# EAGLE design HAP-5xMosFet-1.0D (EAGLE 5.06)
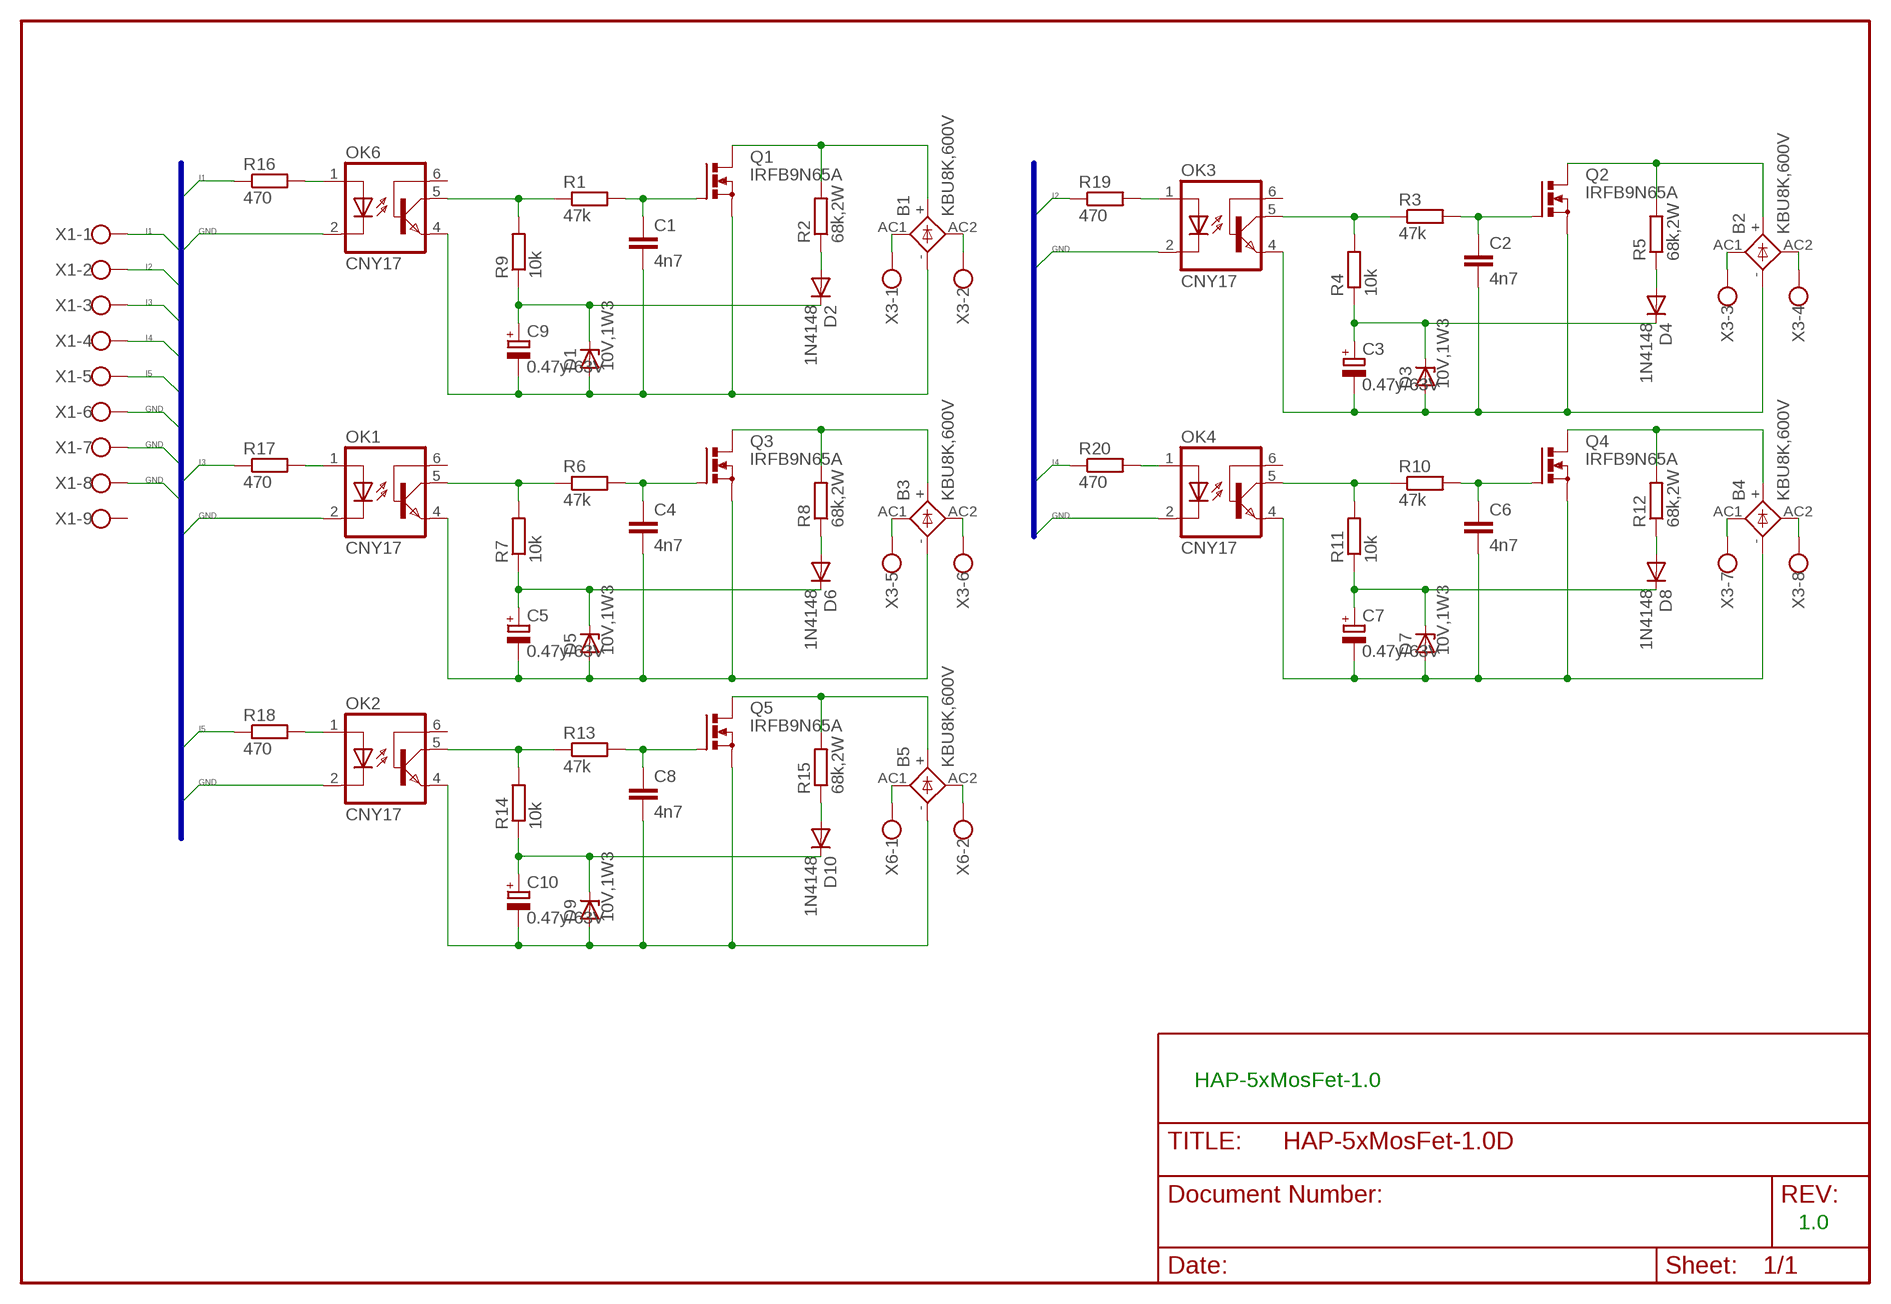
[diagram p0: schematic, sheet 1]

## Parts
B1  KBU8K,600V  KBU  [KBU]
B2  KBU8K,600V  KBU  [KBU]
B3  KBU8K,600V  KBU  [KBU]
B4  KBU8K,600V  KBU  [KBU]
B5  KBU8K,600V  KBU  [KBU]
C1  4n7  C-EU025-025X050  [C025-025X050]
C2  4n7  C-EU025-025X050  [C025-025X050]
C3  0.47y/63V  CPOL-EUE2-5  [E2-5]
C4  4n7  C-EU025-025X050  [C025-025X050]
C5  0.47y/63V  CPOL-EUE2-5  [E2-5]
C6  4n7  C-EU025-025X050  [C025-025X050]
C7  0.47y/63V  CPOL-EUE2-5  [E2-5]
C8  4n7  C-EU025-025X050  [C025-025X050]
C9  0.47y/63V  CPOL-EUE2-5  [E2-5]
C10  0.47y/63V  CPOL-EUE2-5  [E2-5]
D1  10V,1W3  ZENER-DIODEDO34-7  [DO34Z7]
D2  1N4148  BAT81  [DO34-7]
D3  10V,1W3  ZENER-DIODEDO34-7  [DO34Z7]
D4  1N4148  BAT81  [DO34-7]
D5  10V,1W3  ZENER-DIODEDO34-7  [DO34Z7]
D6  1N4148  BAT81  [DO34-7]
D7  10V,1W3  ZENER-DIODEDO34-7  [DO34Z7]
D8  1N4148  BAT81  [DO34-7]
D9  10V,1W3  ZENER-DIODEDO34-7  [DO34Z7]
D10  1N4148  BAT81  [DO34-7]
OK1  CNY17  [DIL06]
OK2  CNY17  [DIL06]
OK3  CNY17  [DIL06]
OK4  CNY17  [DIL06]
OK6  CNY17  [DIL06]
Q1  IRFB9N65A  IRF512  [TO220BV]
Q2  IRFB9N65A  IRF512  [TO220BV]
Q3  IRFB9N65A  IRF512  [TO220BV]
Q4  IRFB9N65A  IRF512  [TO220BV]
Q5  IRFB9N65A  IRF512  [TO220BV]
R1  47k  R-EU_0207/2V  [0207/2V]
R2  68k,2W  R-EU_0411/3V  [0411V]
R3  47k  R-EU_0207/2V  [0207/2V]
R4  10k  R-EU_0207/2V  [0207/2V]
R5  68k,2W  R-EU_0411/3V  [0411V]
R6  47k  R-EU_0207/2V  [0207/2V]
R7  10k  R-EU_0207/2V  [0207/2V]
R8  68k,2W  R-EU_0411/3V  [0411V]
R9  10k  R-EU_0207/2V  [0207/2V]
R10  47k  R-EU_0207/2V  [0207/2V]
R11  10k  R-EU_0207/2V  [0207/2V]
R12  68k,2W  R-EU_0411/3V  [0411V]
R13  47k  R-EU_0207/2V  [0207/2V]
R14  10k  R-EU_0207/2V  [0207/2V]
R15  68k,2W  R-EU_0411/3V  [0411V]
R16  470  R-EU_R0805  [R0805]
R17  470  R-EU_R0805  [R0805]
R18  470  R-EU_R0805  [R0805]
R19  470  R-EU_R0805  [R0805]
R20  470  R-EU_R0805  [R0805]
X1  W237-09P  [W237-9P]
X3  W237-08P  [W237-8P]
X6  W237-08P  [W237-8P]

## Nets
GND: OK1.2(C) OK2.2(C) OK3.2(C) OK4.2(C) OK6.2(C) X1.6 X1.7 X1.8
I1: R16.1 X1.1
I2: R19.1 X1.2
I3: R17.1 X1.3
I4: R20.1 X1.4
I5: R18.1 X1.5
N$1 [Medium]: OK6.5(COL) R1.1 R9.2
N$2 [Medium]: C1.1 Q1.G R1.2
N$3 [Medium]: C9.+ D1.C D2.C R9.1
N$4 [Medium]: OK3.5(COL) R3.1 R4.2
N$5 [Medium]: D2.A R2.1
N$6 [Mains]: B1.+ Q1.D R2.2
N$9 [Medium]: C2.1 Q2.G R3.2
N$10 [Medium]: C3.+ D3.C D4.C R4.1
N$11 [Medium]: D4.A R5.1
N$12 [Mains]: B2.+ Q2.D R5.2
N$15 [Medium]: OK1.5(COL) R6.1 R7.2
N$16 [Medium]: C4.1 Q3.G R6.2
N$17 [Medium]: C5.+ D5.C D6.C R7.1
N$18 [Medium]: D6.A R8.1
N$19 [Mains]: B3.+ Q3.D R8.2
N$22 [Medium]: OK4.5(COL) R10.1 R11.2
N$23 [Medium]: C6.1 Q4.G R10.2
N$24 [Medium]: C7.+ D7.C D8.C R11.1
N$25 [Medium]: D8.A R12.1
N$26 [Mains]: B4.+ Q4.D R12.2
N$29 [Medium]: OK2.5(COL) R13.1 R14.2
N$30 [Medium]: C8.1 Q5.G R13.2
N$31 [Medium]: C10.+ D9.C D10.C R14.1
N$32 [Medium]: D10.A R15.1
N$33 [Mains]: B5.+ Q5.D R15.2
N$36: OK6.1(A) R16.2
N$37: OK1.1(A) R17.2
N$38: OK2.1(A) R18.2
N$39 [Mains]: B1.- C1.2 C9.- D1.A OK6.4(EMI) Q1.S
N$40 [Mains]: B3.- C4.2 C5.- D5.A OK1.4(EMI) Q3.S
N$41 [Mains]: B5.- C8.2 C10.- D9.A OK2.4(EMI) Q5.S
N$42 [Mains]: B2.- C2.2 C3.- D3.A OK3.4(EMI) Q2.S
N$43: OK3.1(A) R19.2
N$44 [Mains]: B4.- C6.2 C7.- D7.A OK4.4(EMI) Q4.S
N$45: OK4.1(A) R20.2
N$71 [Mains]: B1.AC1 X3.1
N$72 [Mains]: B1.AC2 X3.2
N$73 [Mains]: B3.AC1 X3.5
N$74 [Mains]: B3.AC2 X3.6
N$75 [Mains]: B5.AC1 X6.1
N$76 [Mains]: B5.AC2 X6.2
N$77 [Mains]: B2.AC1 X3.3
N$78 [Mains]: B2.AC2 X3.4
N$79 [Mains]: B4.AC1 X3.7
N$80 [Mains]: B4.AC2 X3.8
Unconnected: OK1.6(BAS) OK2.6(BAS) OK3.6(BAS) OK4.6(BAS) OK6.6(BAS) X1.9 X6.3 X6.4 X6.5 X6.6 X6.7 X6.8

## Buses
VCCSUPPLY,GND,O1,O2,O3,O4,O5,O6,O7,O8,I1,I2,I3,I4,I5,I6,I7,I8

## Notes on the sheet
- HAP-5xMosFet-1.0
- 1.0

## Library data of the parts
B1-B5 = rectifier:KBU: DIOTEC RECTIFIER
C1 C2 C4 C6 C8 = rcl:C-EU: CAPACITOR, European symbol
C3 C5 C7 C9 C10 = rcl:CPOL-EU: POLARIZED CAPACITOR, European symbol
D1 D3 D5 D7 D9 = diode:ZENER-DIODE: Z-Diode
D2 D4 D6 D8 D10 = diode:BAT81: DIODE
OK1-OK4 OK6 = optocoupler:CNY17: SIEMENS OPTO COUPLER
Q1-Q5 = transistor-power:IRF512: N-CHANNEL MOS FET
R1-R20 = rcl:R-EU_: RESISTOR, European symbol
X1 = con-wago-508:W237-09P: WAGO SREW CLAMP
X3 X6 = con-wago-508:W237-08P: WAGO SREW CLAMP

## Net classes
1 Mains: width 2.184 mm, clearance 0.508 mm
2 Medium: width 0.508 mm, clearance 0.254 mm

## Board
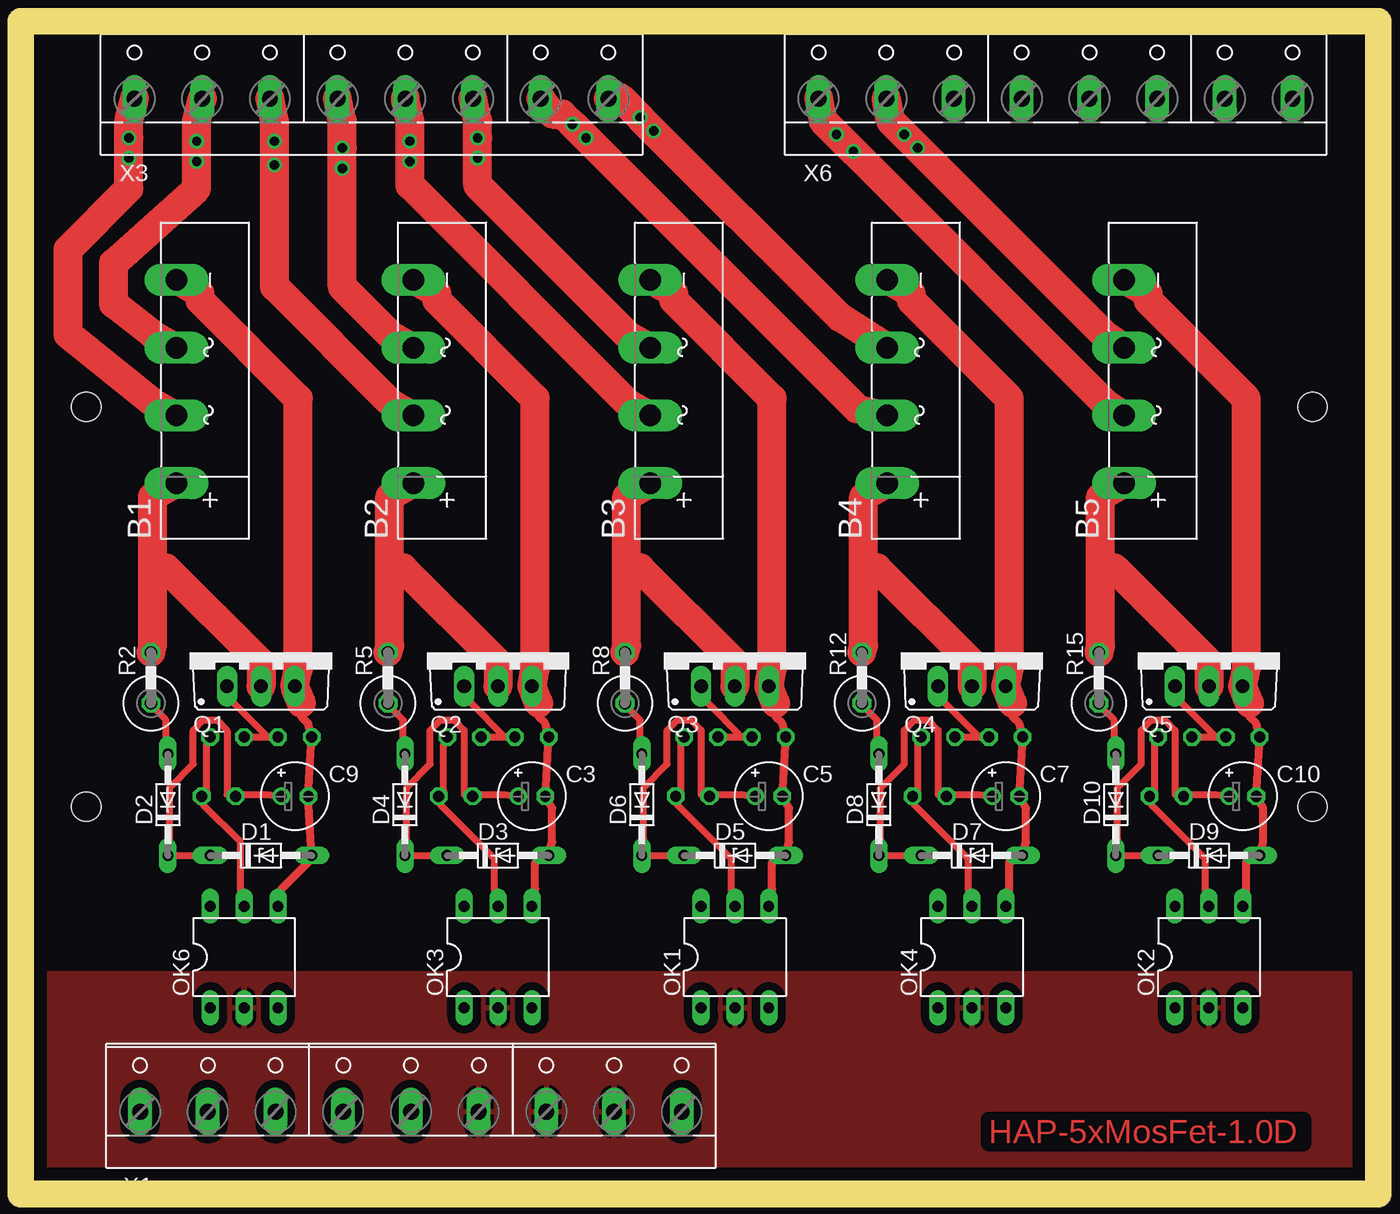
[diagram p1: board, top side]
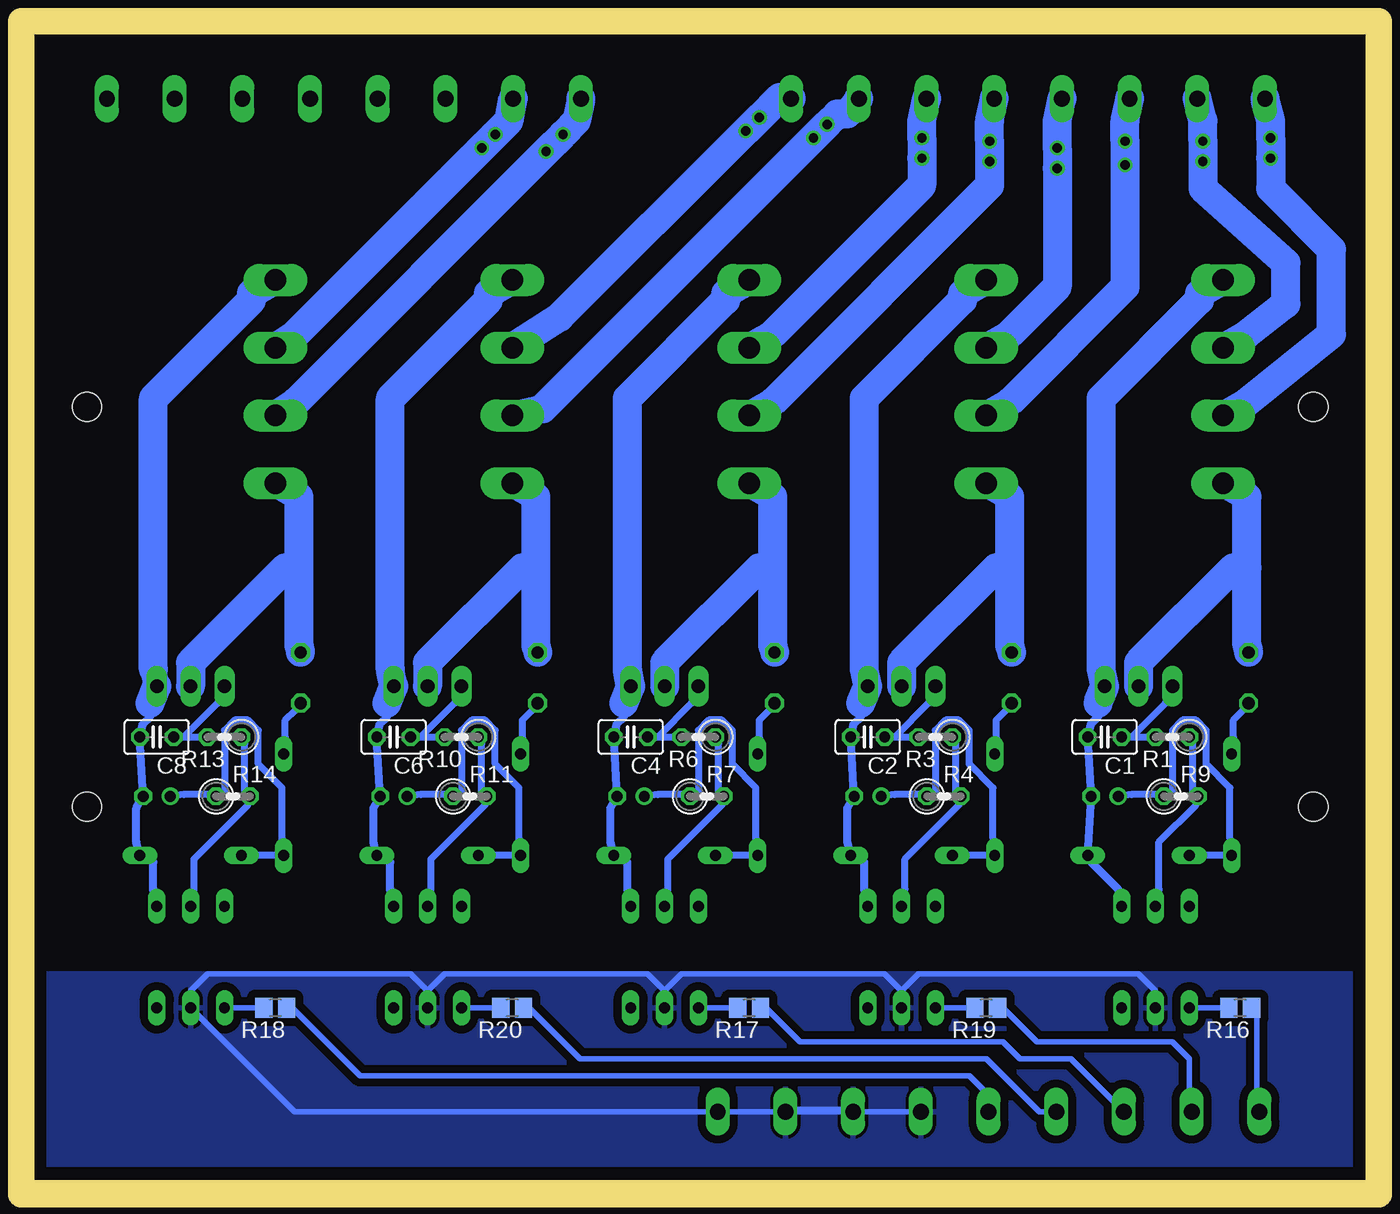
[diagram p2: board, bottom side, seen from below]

Size 100 x 86.08 mm. Coordinates in mm from the lower left corner, seen from the top.
Outline: 100,0 100,86.08 0,86.08 0,0 100,0
Copper layers (1*16): Top 0.035mm / dielectric 1.5mm / Bottom 0.035mm
Design rules "default": minimum track width 10mil, minimum drill 24mil, track to track 8mil, track to pad 8mil, pad to pad 8mil, via to via 8mil, smd to smd 8mil, copper to edge 40mil, drill to drill 8mil, minimum pad ring 10mil, minimum via ring 8mil, stop-mask expansion 4mil, vias tented up to drill 0mil, thermal gap 10mil
Holes 2.2 mm at 3.97,28.05 3.97,58.06 95.98,58.05 95.97,28.05
Milling: 4 lines

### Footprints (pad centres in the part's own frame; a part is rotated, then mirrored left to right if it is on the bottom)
KBU = drill 1.6 long: + -7.62,2.54; - 7.62,2.54; AC1 -2.54,2.54; AC2 2.54,2.54
C025-025X050 = drill 0.813 octagon: 1 -1.27,0; 2 1.27,0
E2-5 = drill 0.813 pad 1.27 round: + -1.016,0 | drill 0.813 pad 1.27 octagon: - 1.016,0
DO34Z7 = drill 0.813 long: A 3.81,0; C -3.81,0
DO34-7 = drill 0.813 long: A 3.81,0; C -3.81,0
DIL06 = drill 0.813 long: 1 -2.54,-3.81; 2 0,-3.81; 3 2.54,-3.81; 4 2.54,3.81; 5 0,3.81; 6 -2.54,3.81
TO220BV = drill 1.016 long: D 0,-2.54; G -2.54,-2.54; S 2.54,-2.54
0207/2V = drill 0.813 octagon: 1 -1.27,0; 2 1.27,0
0411V = drill 0.914 octagon: 1 -2.54,0; 2 1.27,0
R0805 = smd 1.3 x 1.5: 1 -0.85,0; 2 0.85,0
W237-9P = drill 1.194 long: 1 -20.32,-0.635; 2 -15.24,-0.635; 3 -10.16,-0.635; 4 -5.08,-0.635; 5 0,-0.635; 6 5.08,-0.635; 7 10.16,-0.635; 8 15.24,-0.635; 9 20.32,-0.635
W237-8P = drill 1.194 long: 1 -17.78,-0.635; 2 -12.7,-0.635; 3 -7.62,-0.635; 4 -2.54,-0.635; 5 2.54,-0.635; 6 7.62,-0.635; 7 12.7,-0.635; 8 17.78,-0.635

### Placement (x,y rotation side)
B1  13.27,59.95 90 top
B2  31.05,59.95 90 top
B3  48.83,59.95 90 top
B4  66.61,59.95 90 top
B5  84.39,59.95 90 top
C1  19.62,33.28 180 bottom
C2  37.4,33.28 180 bottom
C3  37.4,28.84 0 top
C4  55.18,33.28 180 bottom
C5  55.18,28.84 0 top
C6  72.96,33.28 180 bottom
C7  72.96,28.84 0 top
C8  90.74,33.28 180 bottom
C9  19.62,28.84 0 top
C10  90.74,28.84 0 top
D1  17.08,24.39 0 top
D2  10.09,28.2 90 top
D3  34.86,24.39 0 top
D4  27.88,28.2 90 top
D5  52.64,24.39 0 top
D6  45.66,28.2 90 top
D7  70.42,24.39 0 top
D8  63.44,28.2 90 top
D9  88.2,24.39 0 top
D10  81.22,28.2 90 top
OK1  52.64,16.77 0 top
OK2  88.2,16.77 0 top
OK3  34.86,16.77 0 top
OK4  70.42,16.77 0 top
OK6  15.81,16.77 0 top
Q1  17.08,39.63 0 top
Q2  34.86,39.63 0 top
Q3  52.64,39.63 0 top
Q4  70.42,39.63 0 top
Q5  88.2,39.63 0 top
R1  14.54,33.28 180 bottom
R2  8.82,38.36 90 top
R3  32.32,33.28 180 bottom
R4  31.69,28.84 0 bottom
R5  26.61,38.36 90 top
R6  50.1,33.28 180 bottom
R7  49.47,28.84 0 bottom
R8  44.38,38.36 90 top
R9  13.9,28.84 0 bottom
R10  67.88,33.28 180 bottom
R11  67.25,28.84 0 bottom
R12  62.17,38.36 90 top
R13  85.66,33.28 180 bottom
R14  85.03,28.84 0 bottom
R15  79.95,38.36 90 top
R16  9.46,12.96 180 bottom
R17  46.29,12.96 180 bottom
R18  81.85,12.96 180 bottom
R19  28.51,12.96 180 bottom
R20  64.07,12.96 180 bottom
X1  28.33,5.81 0 top
X3  25.37,81.81 0 top
X6  76.7,81.81 0 top

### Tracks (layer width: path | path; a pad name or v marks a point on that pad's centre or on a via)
GND
  Bottom 0.406: 70.42,14.23 71.69,15.5 86.93,15.5 88.2,14.23 OK2.2 80.41,5.17 X1.6 X1.7 | 70.42,14.23 OK4.2 | 70.42,14.23 69.15,15.5 53.91,15.5 52.64,14.23 | 52.64,14.23 51.37,15.5 36.13,15.5 34.86,14.23 | 34.86,14.23 33.59,15.5 17.08,15.5 15.81,14.23 OK6.2 | X1.7 | X1.7 38.67,5.34 43.75,5.34 X1.8 | 34.86,14.23 OK3.2 | 52.64,14.23 OK1.2
  pour Bottom (isolate 0.61): 0.57,15.5 99.63,15.5 99.63,0.26 0.57,0.26
  pour Top (isolate 0.61): 0.57,15.5 99.63,15.5 99.63,0.26 0.57,0.26
I1
  Bottom 0.406: R16.1 8.19,12.96 8.19,5.17 X1.1
I2
  Bottom 0.406: X1.2 13.27,5.17 13.27,9.15 14.54,10.42 24.7,10.42 27.24,12.96 R19.1
I3
  Bottom 0.406: X1.3 22.16,9.15 25.97,9.15 27.24,10.42 42.48,10.42 45.02,12.96 R17.1
I4
  Bottom 0.406: X1.4 24.53,5.17 28.51,9.15 58.99,9.15 62.8,12.96 R20.1
I5
  Bottom 0.406: X1.5 28.33,6.43 29.78,7.88 75.5,7.88 80.58,12.96 R18.1
N$1
  Top 0.508: OK6.5 15.56,21.85 15.56,25.41 12.76,28.2 R9.2 13.02,29.22 13.02,32.77 R1.1
N$2
  Top 0.508: R1.2 17.59,33.28 | 17.59,33.28 C1.1 | 17.59,33.28 15.05,35.82 Q1.G
N$3
  Top 0.508: D1.C D2.C 10.22,25.66 10.22,29.47 12,31.25 12,33.79 12.76,34.55 13.78,34.55 14.54,33.79 14.54,28.96 R9.1 15.81,28.96 17.59,28.96 C9.+
N$4
  Top 0.508: OK3.5 34.61,21.85 34.61,24.14 30.54,28.2 R4.2 30.8,29.22 30.8,32.77 R3.1
N$5
  Top 0.508: D2.A 9.97,33.28 9.97,34.55 9.21,35.31 R2.1
N$6
  Top 2.184: 8.95,45.98 8.95,51.31 B1.+ | 8.95,45.98 8.95,40.14 R2.2 | Q1.D 17.08,38.87 9.97,45.98 8.95,45.98
N$9
  Top 0.508: R3.2 35.37,33.28 | 35.37,33.28 C2.1 | 35.37,33.28 32.83,35.82 Q2.G
N$10
  Top 0.508: D3.C D4.C 28,25.66 28,29.47 29.78,31.25 29.78,33.79 30.54,34.55 31.56,34.55 32.32,33.79 32.32,28.96 R4.1 33.59,28.96 35.37,28.96 C3.+
N$11
  Top 0.508: D4.A 27.75,33.28 27.75,34.55 26.99,35.31 R5.1
N$12
  Top 2.184: 26.73,45.98 26.73,51.31 B2.+ | 26.73,45.98 26.73,40.14 R5.2 | Q2.D 34.86,38.87 27.75,45.98 26.73,45.98
N$15
  Top 0.508: OK1.5 52.39,21.85 52.39,24.14 48.32,28.2 R7.2 48.58,29.22 48.58,32.77 R6.1
N$16
  Top 0.508: R6.2 53.15,33.28 | 53.15,33.28 C4.1 | 53.15,33.28 50.61,35.82 Q3.G
N$17
  Top 0.508: D5.C D6.C 45.78,25.66 45.78,29.47 47.56,31.25 47.56,33.79 48.32,34.55 49.34,34.55 50.1,33.79 50.1,28.96 R7.1 51.37,28.96 53.15,28.96 C5.+
N$18
  Top 0.508: D6.A 45.53,33.28 45.53,34.55 44.77,35.31 R8.1
N$19
  Top 2.184: 44.51,45.98 44.51,51.31 B3.+ | 44.51,45.98 44.51,40.14 R8.2 | Q3.D 52.64,38.87 45.53,45.98 44.51,45.98
N$22
  Top 0.508: OK4.5 70.17,21.85 70.17,24.14 66.1,28.2 R11.2 66.36,29.22 66.36,32.77 R10.1
N$23
  Top 0.508: R10.2 70.93,33.28 | 70.93,33.28 C6.1 | 70.93,33.28 68.39,35.82 Q4.G
N$24
  Top 0.508: D7.C D8.C 63.56,25.66 63.56,29.47 65.34,31.25 65.34,33.79 66.1,34.55 67.12,34.55 67.88,33.79 67.88,28.96 R11.1 69.15,28.96 70.93,28.96 C7.+
N$25
  Top 0.508: D8.A 63.31,33.28 63.31,34.55 62.55,35.31 R12.1
N$26
  Top 2.184: 62.29,45.98 62.29,51.31 B4.+ | 62.29,45.98 62.29,40.14 R12.2 | Q4.D 70.42,38.87 63.31,45.98 62.29,45.98
N$29
  Top 0.508: OK2.5 87.95,21.85 87.95,24.14 83.88,28.2 R14.2 84.14,29.22 84.14,32.77 R13.1
N$30
  Top 0.508: R13.2 88.71,33.28 | 88.71,33.28 C8.1 | 88.71,33.28 86.17,35.82 Q5.G
N$31
  Top 0.508: D9.C D10.C 81.34,25.66 81.34,29.47 83.12,31.25 83.12,33.79 83.88,34.55 84.9,34.55 85.66,33.79 85.66,28.96 R14.1 86.93,28.96 88.71,28.96 C10.+
N$32
  Top 0.508: D10.A 81.09,33.28 81.09,34.55 80.33,35.31 R15.1
N$33
  Top 2.184: 80.07,45.98 80.07,51.31 B5.+ | 80.07,45.98 80.07,40.14 R15.2 | Q5.D 88.2,38.87 81.09,45.98 80.07,45.98
N$36
  Bottom 0.406: R16.2 OK6.1
N$37
  Bottom 0.406: R17.2 OK1.1
N$38
  Bottom 0.406: R18.2 OK2.1
N$39
  Top 0.61: OK6.4 18.6,21.85 20.64,23.88 D1.A C9.- C1.2 20.64,34.3 20.13,34.8 20.13,35.82
  Top 2.184: 20.13,35.82 Q1.S 19.87,38.36 19.87,58.68 12.51,66.05 12.51,66.55 B1.-
N$40
  Top 0.61: OK1.4 55.43,21.85 55.43,23.88 D5.A 56.7,25.41 56.7,27.95 C5.- C4.2 56.2,34.3 55.69,34.8 55.69,35.82
  Top 2.184: 55.69,35.82 Q3.S 55.43,38.36 55.43,58.68 48.07,66.05 48.07,66.55 B3.-
N$41
  Top 0.61: OK2.4 90.99,21.85 90.99,23.88 D9.A 92.26,25.41 92.26,27.95 C10.- C8.2 91.76,34.3 91.25,34.8 91.25,35.82
  Top 2.184: 91.25,35.82 Q5.S 90.99,38.36 90.99,58.68 83.63,66.05 83.63,66.55 B5.-
N$42
  Top 0.61: OK3.4 37.65,21.85 37.65,23.88 D3.A 38.92,25.41 38.92,27.95 C3.- C2.2 38.42,34.3 37.91,34.8 37.91,35.82
  Top 2.184: 37.91,35.82 Q2.S 37.65,38.36 37.65,58.68 30.29,66.05 30.29,66.55 B2.-
N$43
  Bottom 0.406: R19.2 OK3.1
N$44
  Top 0.61: OK4.4 73.21,21.85 73.21,23.88 D7.A 74.48,25.41 74.48,27.95 C7.- C6.2 73.98,34.3 73.47,34.8 73.47,35.82
  Top 2.184: 73.47,35.82 Q4.S 73.21,38.36 73.21,58.68 65.85,66.05 65.85,66.55 B4.-
N$45
  Bottom 0.406: R20.2 OK4.1
N$46
  Bottom 0.508: 15.81,20.58 15.56,21.85 15.56,25.41 12.76,28.2 12.63,28.84 13.02,29.22 13.02,32.77 13.27,33.28
N$47
  Bottom 0.508: 17.59,33.28 15.81,33.28 | 17.59,33.28 18.35,33.28 | 17.59,33.28 15.05,35.82 14.54,37.09
N$48
  Bottom 0.508: 13.27,24.39 10.09,24.39 10.22,25.66 10.22,29.47 12,31.25 12,33.79 12.76,34.55 13.78,34.55 14.54,33.79 14.54,28.96 15.17,28.84 15.81,28.96 17.59,28.96 18.6,28.84
N$49
  Bottom 0.508: 10.09,32.01 9.97,33.28 9.97,34.55 9.21,35.31 8.82,35.82
N$50
  Bottom 2.184: 8.95,45.98 8.95,51.31 10.73,52.33 | 8.95,45.98 8.95,40.14 8.82,39.63 | 17.08,37.09 17.08,38.87 9.97,45.98 8.95,45.98
N$51
  Bottom 0.508: 34.86,20.58 34.61,21.85 34.61,24.14 30.54,28.2 30.41,28.84 30.8,29.22 30.8,32.77 31.05,33.28
N$52
  Bottom 0.508: 35.37,33.28 33.59,33.28 | 35.37,33.28 36.13,33.28 | 35.37,33.28 32.83,35.82 32.32,37.09
N$53
  Bottom 0.508: 31.05,24.39 27.88,24.39 28,25.66 28,29.47 29.78,31.25 29.78,33.79 30.54,34.55 31.56,34.55 32.32,33.79 32.32,28.96 32.95,28.84 33.59,28.96 35.37,28.96 36.38,28.84
N$54
  Bottom 0.508: 27.88,32.01 27.75,33.28 27.75,34.55 26.99,35.31 26.61,35.82
N$55
  Bottom 2.184: 26.73,45.98 26.73,51.31 28.51,52.33 | 26.73,45.98 26.73,40.14 26.61,39.63 | 34.86,37.09 34.86,38.87 27.75,45.98 26.73,45.98
N$56
  Bottom 0.508: 52.64,20.58 52.39,21.85 52.39,24.14 48.32,28.2 48.2,28.84 48.58,29.22 48.58,32.77 48.83,33.28
N$57
  Bottom 0.508: 53.15,33.28 51.37,33.28 | 53.15,33.28 53.91,33.28 | 53.15,33.28 50.61,35.82 50.1,37.09
N$58
  Bottom 0.508: 48.83,24.39 45.66,24.39 45.78,25.66 45.78,29.47 47.56,31.25 47.56,33.79 48.32,34.55 49.34,34.55 50.1,33.79 50.1,28.96 50.73,28.84 51.37,28.96 53.15,28.96 54.16,28.84
N$59
  Bottom 0.508: 45.66,32.01 45.53,33.28 45.53,34.55 44.77,35.31 44.38,35.82
N$60
  Bottom 2.184: 44.51,45.98 44.51,51.31 46.29,52.33 | 44.51,45.98 44.51,40.14 44.38,39.63 | 52.64,37.09 52.64,38.87 45.53,45.98 44.51,45.98
N$61
  Bottom 0.508: 70.42,20.58 70.17,21.85 70.17,24.14 66.1,28.2 65.97,28.84 66.36,29.22 66.36,32.77 66.61,33.28
N$62
  Bottom 0.508: 70.93,33.28 69.15,33.28 | 70.93,33.28 71.69,33.28 | 70.93,33.28 68.39,35.82 67.88,37.09
N$63
  Bottom 0.508: 66.61,24.39 63.44,24.39 63.56,25.66 63.56,29.47 65.34,31.25 65.34,33.79 66.1,34.55 67.12,34.55 67.88,33.79 67.88,28.96 68.52,28.84 69.15,28.96 70.93,28.96 71.94,28.84
N$64
  Bottom 0.508: 63.44,32.01 63.31,33.28 63.31,34.55 62.55,35.31 62.17,35.82
N$65
  Bottom 2.184: 62.29,45.98 62.29,51.31 64.07,52.33 | 62.29,45.98 62.29,40.14 62.17,39.63 | 70.42,37.09 70.42,38.87 63.31,45.98 62.29,45.98
N$66
  Bottom 0.508: 88.2,20.58 87.95,21.85 87.95,24.14 83.88,28.2 83.75,28.84 84.14,29.22 84.14,32.77 84.39,33.28
N$67
  Bottom 0.508: 88.71,33.28 86.93,33.28 | 88.71,33.28 89.47,33.28 | 88.71,33.28 86.17,35.82 85.66,37.09
N$68
  Bottom 0.508: 84.39,24.39 81.22,24.39 81.34,25.66 81.34,29.47 83.12,31.25 83.12,33.79 83.88,34.55 84.9,34.55 85.66,33.79 85.66,28.96 86.3,28.84 86.93,28.96 88.71,28.96 89.72,28.84
N$69
  Bottom 0.508: 81.22,32.01 81.09,33.28 81.09,34.55 80.33,35.31 79.95,35.82
N$70
  Bottom 2.184: 80.07,45.98 80.07,51.31 81.85,52.33 | 80.07,45.98 80.07,40.14 79.95,39.63 | 88.2,37.09 88.2,38.87 81.09,45.98 80.07,45.98
N$71  (via drill 0.7)
  Top 2.184: X3.1 7.17,79.51 v7.17,78.24 7.17,74.43 2.6,69.86 2.6,63.51 8.95,58.43 B1.AC1
  Bottom 0.406: v7.17,78.24 v7.17,76.71
  Bottom 2.184: X3.1 7.17,79.51 v7.17,78.24 v7.17,76.71 7.17,74.43 2.6,69.86 2.6,63.51 8.95,58.43 B1.AC1
N$72  (via drill 0.7)
  Top 2.184: X3.2 12.25,79.51 v12.25,77.98 12.25,74.43 6.03,68.84 6.03,65.79 8.95,63.51 B1.AC2
  Bottom 0.406: v12.25,77.98 v12.25,76.46
  Bottom 2.184: X3.2 12.25,79.51 v12.25,77.98 v12.25,76.46 12.25,74.43 6.03,68.84 6.03,65.79 8.95,63.51 B1.AC2
N$73  (via drill 0.7)
  Top 2.184: X3.5 28.26,79.51 v28.26,77.98 28.26,74.68 44.51,58.43 B3.AC1
  Bottom 0.406: v28.26,77.98 v28.26,76.46
  Bottom 2.184: X3.5 28.26,79.51 v28.26,77.98 v28.26,76.46 28.26,74.68 44.51,58.43 B3.AC1
N$74  (via drill 0.7)
  Top 2.184: X3.6 33.34,79.51 v33.34,78.24 33.34,74.68 44.51,63.51 B3.AC2
  Bottom 0.406: v33.34,78.24 v33.34,76.71
  Bottom 2.184: X3.6 33.34,79.51 v33.34,78.24 v33.34,76.71 33.34,74.68 44.51,63.51 B3.AC2
N$75  (via drill 0.7)
  Top 2.184: X6.1 59.24,79.51 v61.53,77.22 80.33,58.43 B5.AC1
  Bottom 0.406: 59.24,79.51 60.26,79.51 v60.26,78.49
  Bottom 2.184: X6.1 59.24,79.51 v60.26,78.49 v61.53,77.22 80.33,58.43 B5.AC1
N$76  (via drill 0.7)
  Top 2.184: X6.2 64.32,79.51 v65.34,78.49 80.33,63.51 B5.AC2
  Bottom 0.406: v65.34,78.49 66.36,78.49 v66.36,77.48
  Bottom 2.184: X6.2 64.32,79.51 v65.34,78.49 v66.36,77.48 80.33,63.51 B5.AC2
N$77  (via drill 0.7)
  Top 2.184: X3.3 18.1,79.51 v18.1,77.98 18.1,67.06 26.73,58.43 B2.AC1
  Bottom 0.406: v18.1,77.98 v18.1,76.21
  Bottom 2.184: X3.3 18.1,79.51 v18.1,77.98 v18.1,76.21 18.1,67.06 26.73,58.43 B2.AC1
N$78  (via drill 0.7)
  Top 2.184: X3.4 23.18,79.51 v23.18,77.48 23.18,67.06 26.73,63.51 B2.AC2
  Bottom 0.406: v23.18,77.48 v23.18,75.95
  Bottom 2.184: X3.4 23.18,79.51 v23.18,77.48 v23.18,75.95 23.18,67.06 26.73,63.51 B2.AC2
N$79  (via drill 0.7)
  Top 2.184: X3.7 38.92,80.02 39.69,80.02 v40.45,79.25 61.78,57.92 B4.AC1
  Bottom 0.406: v40.45,79.25 41.46,79.25 v41.46,78.24
  Bottom 2.184: X3.7 38.92,80.02 39.69,80.02 v40.45,79.25 v41.46,78.24 61.78,57.92 B4.AC1
N$80  (via drill 0.7)
  Top 2.184: X3.8 44,81.29 v45.53,79.76 60.51,64.78 B4.AC2
  Bottom 0.406: v45.53,79.76 46.54,79.76 v46.54,78.75
  Bottom 2.184: X3.8 44,81.29 v45.53,79.76 v46.54,78.75 60.51,64.78 B4.AC2
N$81
  Bottom 0.61: 18.35,20.58 18.6,21.85 20.64,23.88 20.89,24.39 20.64,28.84 20.89,33.28 20.64,34.3 20.13,34.8 20.13,35.82
  Bottom 2.184: 20.13,35.82 19.62,37.09 19.87,38.36 19.87,58.68 12.51,66.05 12.51,66.55 10.73,67.57
N$82
  Bottom 0.61: 55.18,20.58 55.43,21.85 55.43,23.88 56.45,24.39 56.7,25.41 56.7,27.95 56.2,28.84 56.45,33.28 56.2,34.3 55.69,34.8 55.69,35.82
  Bottom 2.184: 55.69,35.82 55.18,37.09 55.43,38.36 55.43,58.68 48.07,66.05 48.07,66.55 46.29,67.57
N$83
  Bottom 0.61: 90.74,20.58 90.99,21.85 90.99,23.88 92.01,24.39 92.26,25.41 92.26,27.95 91.76,28.84 92.01,33.28 91.76,34.3 91.25,34.8 91.25,35.82
  Bottom 2: 90.74,37.09 90.99,38.36
  Bottom 2.184: 91.25,35.82 90.74,37.09 | 90.99,38.36 90.99,58.68 83.63,66.05 83.63,66.55 81.85,67.57
N$84
  Bottom 0.61: 37.4,20.58 37.65,21.85 37.65,23.88 38.67,24.39 38.92,25.41 38.92,27.95 38.42,28.84 38.67,33.28 38.42,34.3 37.91,34.8 37.91,35.82
  Bottom 2.184: 37.91,35.82 37.4,37.09 37.65,38.36 37.65,58.68 30.29,66.05 30.29,66.55 28.51,67.57
N$85
  Bottom 0.61: 72.96,20.58 73.21,21.85 73.21,23.88 74.23,24.39 74.48,25.41 74.48,27.95 73.98,28.84 74.23,33.28 73.98,34.3 73.47,34.8 73.47,35.82
  Bottom 2.184: 73.47,35.82 72.96,37.09 73.21,38.36 73.21,58.68 65.85,66.05 65.85,66.55 64.07,67.57

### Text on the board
Top: HAP-5xMosFet-1.0D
